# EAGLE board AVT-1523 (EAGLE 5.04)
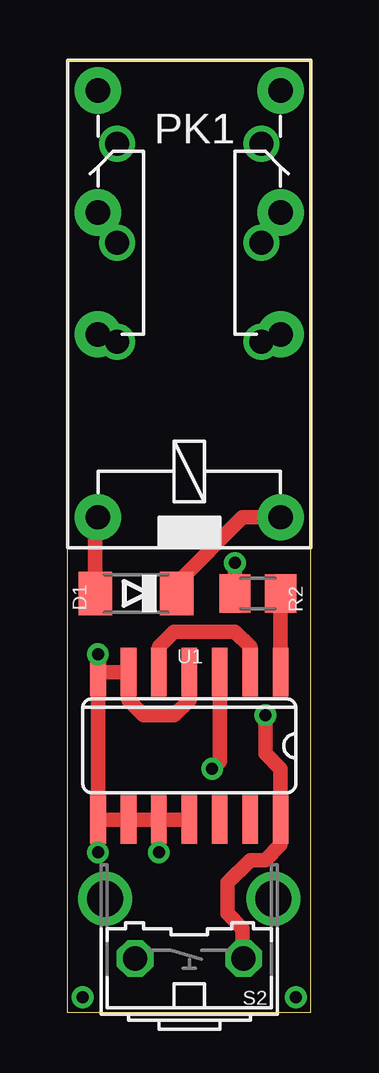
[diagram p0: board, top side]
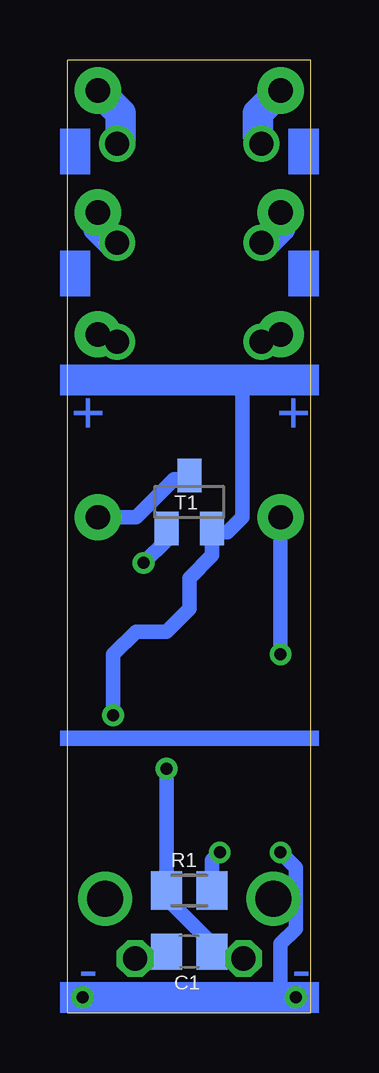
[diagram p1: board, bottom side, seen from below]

Size 10.16 x 39.69 mm. Coordinates in mm from the lower left corner, seen from the top.
Outline: 0,39.69 10.16,39.69 10.16,0 0,0 0,39.69
Copper layers (1*16): Top 0.035mm / dielectric 1.5mm / Bottom 0.035mm
Design rules "default": minimum track width 10mil, minimum drill 24mil, track to track 8mil, track to pad 8mil, pad to pad 8mil, via to via 8mil, smd to smd 8mil, copper to edge 40mil, drill to drill 8mil, minimum pad ring 10mil, minimum via ring 8mil, stop-mask expansion 4mil, vias tented up to drill 0mil, thermal gap 10mil

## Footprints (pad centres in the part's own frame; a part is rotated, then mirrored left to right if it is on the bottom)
C0805 = smd 1.3 x 1.5: 1 -0.95,0; 2 0.95,0
MINIMELF = smd 1.4 x 1.8: A 1.7,0; C -1.7,0
351 = drill 1.016 pad 1.93 round: 1 -3.81,-3.81; 16 -3.81,3.81; O1 8.89,-3.81; O2 8.89,3.81; P1 3.81,-3.81; P2 3.81,3.81; S1 13.97,-3.81; S2 13.97,3.81
M0805 = smd 1.3 x 1.6: 1 -0.95,0; 2 0.95,0
B3F-31XX = drill 1.016 octagon: 1 -2.261,-1.245; 2 2.261,-1.245 | drill 1.499 pad 2.159 round: 3 -3.505,1.245; 4 3.505,1.245
SOT23-BEC = smd 1 x 1.4: B -0.95,-1.1; C 0,1.1; E 0.95,-1.1
SO14 = smd 0.66 x 2.032: 1 -3.81,-3.073; 2 -2.54,-3.073; 3 -1.27,-3.073; 4 0,-3.073; 5 1.27,-3.073; 6 2.54,-3.073; 7 3.81,-3.073; 8 3.81,3.073; 9 2.54,3.073; 10 1.27,3.073; 11 0,3.073; 12 -1.27,3.073; 13 -2.54,3.073; 14 -3.81,3.073

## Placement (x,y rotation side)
C1  100nF  [C0805]  5.08,2.54 0 bottom
D1  4148  [MINIMELF]  2.86,17.46 180 top
PK1  351  [351]  5.08,24.45 90 top
R1  10k  [M0805]  5.08,5.08 180 bottom
R2  4,7k  [M0805]  7.94,17.46 0 top
S2  [B3F-31XX]  5.08,3.49 0 top
T1  BC807  [SOT23-BEC]  5.08,21.27 0 bottom
U1  4013  [SO14]  5.08,11.11 180 top

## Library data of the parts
C1 R1 R2 = rcl
D1 = diode
PK1 = relay
S2 = switch-omron
T1 = transistor-pnp
U1 = 40xx

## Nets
N$1: D1.A PK1.16 R1.1 U1.4 U1.6 U1.7 U1.8 U1.9 U1.10 U1.11
N$2: R2.2 U1.1
N$4: U1.2 U1.5
N$5: C1.2 R1.2 S2.1 U1.3
N$7: R2.1 T1.B
N$8: C1.1 S2.2 T1.E U1.14
N$9: D1.C PK1.1 T1.C

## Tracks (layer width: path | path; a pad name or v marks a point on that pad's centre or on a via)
N$1  (via drill 0.5)
  Top 0.61: U1.7 1.27,13.97 | 3.81,7.94 3.71,8.04 U1.9 2.54,8.25 2.32,8.04 U1.8 U1.7 | U1.11 5.08,8.25 4.86,8.04 U1.10 3.81,7.94 | U1.7 2.44,14.19 2.54,14.29 U1.6 2.54,13.02 3.18,12.38 4.45,12.38 5.08,13.02 U1.4 5.08,14.29 | 3.81,7.94 v3.81,6.67 | U1.7 v1.27,14.92 | D1.A 1.16,20.43 PK1.16
  Bottom 0.61: R1.1 4.13,6.35 v3.81,6.67 | v1.27,14.92 PK1.16 | v1.27,6.67 0.64,6.03 0.64,3.49 1.27,2.86 1.27,0.63 v0.64,0.63 | v0.64,0.63 0.32,0.63 | v0.64,0.63 2.54,0.63
N$2
  Top 0.61: R2.2 U1.1
N$4
  Top 0.61: 3.81,14.29 U1.5 3.81,15.24 4.45,15.87 6.99,15.87 7.62,15.24 U1.2
N$5  (via drill 0.5)
  Top 0.61: U1.3 6.35,10.48 v6.03,10.16
  Bottom 0.61: 4.13,2.22 2.86,2.22 2.83,2.25 S2.1 4.1,2.25 4.13,2.22 | 4.13,2.22 C1.2 4.13,2.86 | 4.13,2.86 6.03,4.76 R1.2 6.03,4.76 | 4.13,2.22 4.13,2.86 | 4.13,2.86 6.03,4.76 | 6.03,4.76 v6.03,10.16
N$7  (via drill 0.5)
  Top 0.61: R2.1 v6.99,18.73
  Bottom 0.61: T1.B 5.86,20.17 6.03,19.68 v6.99,18.73
N$8  (via drill 0.5)
  Top 0.61: 8.89,7.94 8.89,6.98 8.26,6.35 7.62,6.35 6.67,5.4 6.67,4.13 7.3,3.49 7.3,2.22 7.33,2.25 S2.2 | v8.26,12.38 8.26,10.8 8.89,10.16 8.89,7.94 | 8.89,7.94 U1.14
  Bottom 0.61: C1.1 6.03,2.22 6.06,2.25 6.67,2.22 | 6.67,2.22 6.64,2.25 | 6.67,2.22 S2.2 | T1.E 4.13,19.05 5.08,18.1 5.08,16.83 6.03,15.87 7.3,15.87 8.26,14.92 v8.26,12.38
N$9
  Top 0.61: PK1.1 7.3,20.64 4.56,17.89 4.56,17.57 4.45,17.46 D1.C
  Bottom 0.61: T1.C 5.08,22.22 5.72,22.22 7.3,20.64 PK1.1
N$15
  Bottom 0.61: 0.64,11.43 9.53,11.43
N$16  (via drill 1)
  other vias: 2.06,32.07
N$17  (via drill 1)
  other vias: 2.06,36.19
N$18  (via drill 1)
  other vias: 2.06,27.94
N$19  (via drill 1)
  other vias: 8.1,27.94
N$20  (via drill 1)
  other vias: 8.1,32.07
N$21  (via drill 1)
  other vias: 8.1,36.19
N$22
  Bottom 1.27: 2.22,36.51 2.22,37.46 1.59,38.1
N$23
  Bottom 1.27: 7.94,36.19 7.94,37.46 8.57,38.1
N$24
  Bottom 1.27: 1.91,32.07 1.27,32.7
N$25
  Bottom 1.27: 8.26,32.07 8.89,32.7
N$26
  Top 0.61: 1.27,6.67 1.27,7.94
N$27  (via drill 0.5)
  other vias: 9.53,0.63
N$28
  Bottom 0.61: 4.13,20 3.49,20 2.86,20.64 2.86,21.27 | 2.86,20.96 2.86,21.27 | 2.86,21.27 2.86,26.35 | 4.13,20 4.13,20.32 | 4.13,20 4.13,19.05
(copper drawn outside any net)
  shapes: Bottom area x15

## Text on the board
Bottom: + | + | - | -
